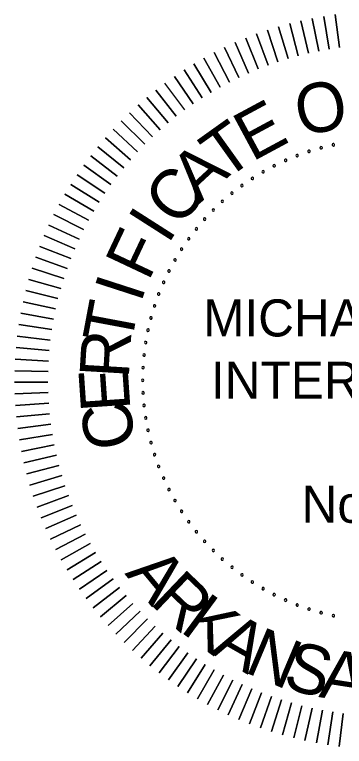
# Model space of a CAD drawing. Extents: x 185 to 5012, y 113 to 2127.
# Drawn here: x 2660.2 to 2771.5, y 179.4 to 426.3 of the extents above; entities that cross this region are included whole.
import ezdxf

# ---------------------------------------------------------------- set-up
doc = ezdxf.new("R2010")
doc.units = 0
doc.layers.add('STAMP_BOL', color=7, linetype='Continuous')

msp = doc.modelspace()

# ---------------------------------------------------------------- linework, layer by layer
at = {"layer": 'STAMP_BOL'}
for points in [[(2762.82, 414.03), (2760.66, 425.04)], [(2760.66, 425.04), (2762.82, 414.03)], [(2766.33, 414.66), (2764.51, 425.73)], [(2764.51, 425.73), (2766.33, 414.66)], [(2769.84, 415.18), (2768.38, 426.3)], [(2768.38, 426.3), (2769.84, 415.18)], [(2752.47, 411.48), (2749.28, 422.24)], [(2749.28, 422.24), (2752.47, 411.48)], [(2755.89, 412.44), (2753.04, 423.29)], [(2753.04, 423.29), (2755.89, 412.44)], [(2759.35, 413.28), (2756.84, 424.22)], [(2756.84, 424.22), (2759.35, 413.28)], [(2745.71, 409.24), (2741.85, 419.78)], [(2741.85, 419.78), (2745.71, 409.24)], [(2749.07, 410.41), (2745.55, 421.07)], [(2745.55, 421.07), (2749.07, 410.41)], [(2742.39, 407.97), (2738.21, 418.38)], [(2738.21, 418.38), (2742.39, 407.97)], [(2735.88, 405.11), (2731.05, 415.23)], [(2731.05, 415.23), (2735.88, 405.11)], [(2739.12, 406.59), (2734.6, 416.86)], [(2734.6, 416.86), (2739.12, 406.59)], [(2732.7, 403.52), (2727.55, 413.49)], [(2727.55, 413.49), (2732.7, 403.52)], [(2729.56, 401.84), (2724.1, 411.65)], [(2724.1, 411.65), (2729.56, 401.84)], [(2723.46, 398.19), (2717.4, 407.63)], [(2717.4, 407.63), (2723.46, 398.19)], [(2726.48, 400.06), (2720.72, 409.69)], [(2720.72, 409.69), (2726.48, 400.06)], [(2720.5, 396.22), (2714.14, 405.46)], [(2714.14, 405.46), (2720.5, 396.22)], [(2717.6, 394.16), (2710.95, 403.2)], [(2714.77, 392), (2707.84, 400.83)], [(2707.84, 400.83), (2714.77, 392)], [(2712.01, 389.77), (2704.8, 398.37)], [(2704.8, 398.37), (2712.01, 389.77)], [(2709.31, 387.44), (2701.85, 395.82)], [(2701.85, 395.82), (2709.31, 387.44)], [(2706.7, 385.03), (2698.97, 393.17)], [(2698.97, 393.17), (2706.7, 385.03)], [(2704.16, 382.54), (2696.18, 390.43)], [(2696.18, 390.43), (2704.16, 382.54)], [(2701.7, 379.97), (2693.47, 387.61)], [(2693.47, 387.61), (2701.7, 379.97)], [(2699.32, 377.33), (2690.86, 384.71)], [(2690.86, 384.71), (2699.32, 377.33)], [(2697.02, 374.61), (2688.34, 381.72)], [(2688.34, 381.72), (2697.02, 374.61)], [(2694.81, 371.83), (2685.91, 378.65)], [(2685.91, 378.65), (2694.81, 371.83)], [(2692.69, 368.97), (2683.58, 375.51)], [(2683.58, 375.51), (2692.69, 368.97)], [(2690.67, 366.05), (2681.35, 372.3)], [(2681.35, 372.3), (2690.67, 366.05)], [(2688.73, 363.06), (2679.22, 369.02)], [(2679.22, 369.02), (2688.73, 363.06)], [(2686.89, 360.02), (2677.2, 365.68)], [(2677.2, 365.68), (2686.89, 360.02)], [(2685.14, 356.92), (2675.28, 362.27)], [(2675.28, 362.27), (2685.14, 356.92)], [(2683.5, 353.77), (2673.47, 358.81)], [(2673.47, 358.81), (2683.5, 353.77)], [(2681.95, 350.57), (2671.77, 355.29)], [(2671.77, 355.29), (2681.95, 350.57)], [(2680.5, 347.32), (2670.18, 351.72)], [(2670.18, 351.72), (2680.5, 347.32)], [(2679.16, 344.02), (2668.7, 348.1)], [(2668.7, 348.1), (2679.16, 344.02)], [(2677.92, 340.69), (2667.34, 344.43)], [(2667.34, 344.43), (2677.92, 340.69)], [(2676.79, 337.32), (2666.1, 340.73)], [(2666.1, 340.73), (2676.79, 337.32)], [(2675.76, 333.91), (2664.97, 336.98)], [(2664.97, 336.98), (2675.76, 333.91)], [(2674.84, 330.48), (2663.96, 333.21)], [(2663.96, 333.21), (2674.84, 330.48)], [(2674.03, 327.01), (2663.07, 329.4)], [(2663.07, 329.4), (2674.03, 327.01)], [(2673.33, 323.53), (2662.29, 325.57)], [(2662.29, 325.57), (2673.33, 323.53)], [(2672.74, 320.02), (2661.64, 321.71)], [(2661.64, 321.71), (2672.74, 320.02)], [(2672.26, 316.5), (2661.11, 317.84)], [(2661.11, 317.84), (2672.26, 316.5)], [(2671.89, 312.96), (2660.71, 313.95)], [(2660.71, 313.95), (2671.89, 312.96)], [(2671.63, 309.41), (2660.42, 310.05)], [(2660.42, 310.05), (2671.63, 309.41)], [(2671.48, 305.86), (2660.26, 306.15)], [(2660.26, 306.15), (2671.48, 305.86)], [(2671.44, 302.3), (2660.22, 302.24)], [(2660.22, 302.24), (2671.44, 302.3)], [(2671.52, 298.75), (2660.3, 298.33)], [(2660.3, 298.33), (2671.52, 298.75)], [(2671.71, 295.19), (2660.51, 294.43)], [(2660.51, 294.43), (2671.71, 295.19)], [(2672, 291.65), (2660.84, 290.53)], [(2660.84, 290.53), (2672, 291.65)], [(2672.41, 288.12), (2661.29, 286.65)], [(2661.29, 286.65), (2672.41, 288.12)], [(2672.94, 284.6), (2661.86, 282.78)], [(2661.86, 282.78), (2672.94, 284.6)], [(2673.57, 281.1), (2662.55, 278.93)], [(2662.55, 278.93), (2673.57, 281.1)], [(2674.31, 277.62), (2663.37, 275.11)], [(2663.37, 275.11), (2674.31, 277.62)], [(2675.16, 274.17), (2664.3, 271.31)], [(2664.3, 271.31), (2675.16, 274.17)], [(2676.11, 270.74), (2665.35, 267.55)], [(2665.35, 267.55), (2676.11, 270.74)], [(2677.18, 267.35), (2666.52, 263.82)], [(2666.52, 263.82), (2677.18, 267.35)], [(2678.35, 263.99), (2667.81, 260.13)], [(2667.81, 260.13), (2678.35, 263.99)], [(2679.63, 260.67), (2669.21, 256.48)], [(2669.21, 256.48), (2679.63, 260.67)], [(2681, 257.39), (2670.73, 252.88)], [(2670.73, 252.88), (2681, 257.39)], [(2682.49, 254.16), (2672.36, 249.32)], [(2672.36, 249.32), (2682.49, 254.16)], [(2684.07, 250.97), (2674.1, 245.82)], [(2674.1, 245.82), (2684.07, 250.97)], [(2685.75, 247.84), (2675.95, 242.38)], [(2675.95, 242.38), (2685.75, 247.84)], [(2687.53, 244.76), (2677.9, 238.99)], [(2677.9, 238.99), (2687.53, 244.76)], [(2689.41, 241.73), (2679.96, 235.67)], [(2679.96, 235.67), (2689.41, 241.73)], [(2691.37, 238.77), (2682.13, 232.41)], [(2682.13, 232.41), (2691.37, 238.77)], [(2693.44, 235.87), (2684.39, 229.23)], [(2684.39, 229.23), (2693.44, 235.87)], [(2695.59, 233.04), (2686.76, 226.11)], [(2686.76, 226.11), (2695.59, 233.04)], [(2697.83, 230.28), (2689.22, 223.08)], [(2689.22, 223.08), (2697.83, 230.28)], [(2700.15, 227.59), (2691.77, 220.12)], [(2691.77, 220.12), (2700.15, 227.59)], [(2702.56, 224.97), (2694.42, 217.24)], [(2694.42, 217.24), (2702.56, 224.97)], [(2705.05, 222.43), (2697.16, 214.45)], [(2697.16, 214.45), (2705.05, 222.43)], [(2707.62, 219.97), (2699.98, 211.75)], [(2699.98, 211.75), (2707.62, 219.97)], [(2702.89, 209.13), (2710.26, 217.59)], [(2710.26, 217.59), (2702.89, 209.13)], [(2705.87, 206.61), (2712.98, 215.29)], [(2712.98, 215.29), (2705.87, 206.61)], [(2708.94, 204.18), (2715.77, 213.09)], [(2715.77, 213.09), (2708.94, 204.18)], [(2712.08, 201.85), (2718.62, 210.97)], [(2718.62, 210.97), (2712.08, 201.85)], [(2715.29, 199.62), (2721.54, 208.94)], [(2721.54, 208.94), (2715.29, 199.62)], [(2718.57, 197.49), (2724.53, 207)], [(2724.53, 207), (2718.57, 197.49)], [(2721.91, 195.47), (2727.57, 205.16)], [(2727.57, 205.16), (2721.91, 195.47)], [(2725.32, 193.55), (2730.67, 203.42)], [(2730.67, 203.42), (2725.32, 193.55)], [(2728.78, 191.74), (2733.82, 201.77)], [(2733.82, 201.77), (2728.78, 191.74)], [(2732.3, 190.04), (2737.02, 200.22)], [(2737.02, 200.22), (2732.3, 190.04)], [(2735.88, 188.45), (2740.27, 198.78)], [(2740.27, 198.78), (2735.88, 188.45)], [(2739.5, 186.98), (2743.57, 197.43)], [(2743.57, 197.43), (2739.5, 186.98)], [(2743.16, 185.61), (2746.9, 196.19)], [(2746.9, 196.19), (2743.16, 185.61)], [(2746.87, 184.37), (2750.27, 195.06)], [(2750.27, 195.06), (2746.87, 184.37)], [(2750.61, 183.24), (2753.68, 194.03)], [(2753.68, 194.03), (2750.61, 183.24)], [(2754.38, 182.23), (2757.11, 193.12)], [(2757.11, 193.12), (2754.38, 182.23)], [(2758.19, 181.34), (2760.58, 192.3)], [(2760.58, 192.3), (2758.19, 181.34)], [(2762.02, 180.57), (2764.06, 191.6)], [(2764.06, 191.6), (2762.02, 180.57)], [(2765.88, 179.92), (2767.57, 191.01)], [(2767.57, 191.01), (2765.88, 179.92)], [(2769.75, 179.39), (2771.1, 190.53)], [(2771.1, 190.53), (2769.75, 179.39)]]:
    msp.add_lwpolyline(points, dxfattribs=at)
for centre, start, end in [((2767.77, 382.37), 12, 192), ((2759.56, 380.17), 18, 198), ((2759.56, 380.17), 198, 18), ((2763.64, 381.38), 15, 195), ((2763.64, 381.38), 195, 15), ((2767.77, 382.37), 192, 12), ((2755.55, 378.75), 21, 201), ((2755.55, 378.75), 201, 21), ((2747.79, 375.3), 27, 207), ((2747.79, 375.3), 207, 27), ((2751.63, 377.13), 24, 204), ((2751.63, 377.13), 204, 24), ((2744.05, 373.27), 30, 210), ((2744.05, 373.27), 210, 30), ((2740.43, 371.04), 33, 213), ((2740.43, 371.04), 213, 33), ((2736.92, 368.64), 36, 216), ((2736.92, 368.64), 216, 36), ((2733.55, 366.05), 39, 219), ((2733.55, 366.05), 219, 39), ((2730.32, 363.29), 42, 222), ((2730.32, 363.29), 222, 42), ((2727.23, 360.36), 45, 225), ((2727.23, 360.36), 225, 45), ((2724.31, 357.28), 48, 228), ((2724.31, 357.28), 228, 48), ((2721.54, 354.04), 51, 231), ((2721.54, 354.04), 231, 51), ((2718.96, 350.67), 54, 234), ((2718.96, 350.67), 234, 54), ((2716.55, 347.16), 57, 237), ((2716.55, 347.16), 237, 57), ((2714.33, 343.54), 60, 240), ((2714.33, 343.54), 240, 60), ((2712.3, 339.8), 63, 243), ((2712.3, 339.8), 243, 63), ((2710.47, 335.97), 66, 246), ((2710.47, 335.97), 246, 66), ((2708.84, 332.04), 69, 249), ((2708.84, 332.04), 249, 69), ((2707.42, 328.03), 72, 252), ((2707.42, 328.03), 252, 72), ((2706.21, 323.95), 75, 255), ((2706.21, 323.95), 255, 75), ((2705.22, 319.82), 78, 258), ((2705.22, 319.82), 258, 78), ((2704.44, 315.64), 81, 261), ((2704.44, 315.64), 261, 81), ((2703.89, 311.42), 84, 264), ((2703.89, 311.42), 264, 84), ((2703.56, 307.18), 87, 267), ((2703.56, 307.18), 267, 87), ((2703.44, 302.93), 90, 270), ((2703.44, 302.93), 270, 90), ((2703.56, 298.68), 93, 273), ((2703.56, 298.68), 273, 93), ((2703.89, 294.44), 96, 276), ((2703.89, 294.44), 276, 96), ((2704.44, 290.23), 99, 279), ((2704.44, 290.23), 279, 99), ((2705.22, 286.05), 102, 282), ((2705.22, 286.05), 282, 102), ((2706.21, 281.91), 105, 285), ((2706.21, 281.91), 285, 105), ((2707.42, 277.84), 108, 288), ((2707.42, 277.84), 288, 108), ((2708.84, 273.83), 111, 291), ((2708.84, 273.83), 291, 111), ((2710.47, 269.9), 114, 294), ((2710.47, 269.9), 294, 114), ((2712.3, 266.06), 117, 297), ((2712.3, 266.06), 297, 117), ((2714.33, 262.32), 120, 300), ((2714.33, 262.32), 300, 120), ((2716.55, 258.7), 123, 303), ((2716.55, 258.7), 303, 123), ((2718.96, 255.2), 126, 306), ((2718.96, 255.2), 306, 126), ((2721.54, 251.82), 129, 309), ((2721.54, 251.82), 309, 129), ((2724.31, 248.59), 132, 312), ((2724.31, 248.59), 312, 132), ((2727.23, 245.5), 135, 315), ((2727.23, 245.5), 315, 135), ((2730.32, 242.58), 138, 318), ((2730.32, 242.58), 318, 138), ((2733.55, 239.82), 141, 321), ((2733.55, 239.82), 321, 141), ((2736.92, 237.23), 144, 324), ((2736.92, 237.23), 324, 144), ((2740.43, 234.82), 147, 327), ((2740.43, 234.82), 327, 147), ((2744.05, 232.6), 150, 330), ((2744.05, 232.6), 330, 150), ((2747.79, 230.57), 153, 333), ((2747.79, 230.57), 333, 153), ((2751.63, 228.74), 156, 336), ((2751.63, 228.74), 336, 156), ((2755.55, 227.11), 159, 339), ((2755.55, 227.11), 339, 159), ((2759.56, 225.69), 162, 342), ((2759.56, 225.69), 342, 162), ((2763.64, 224.48), 345, 165), ((2763.64, 224.48), 165, 345), ((2767.77, 223.49), 168, 348), ((2767.77, 223.49), 348, 168)]:
    msp.add_arc(centre, 0.417, start, end, dxfattribs=at)

# ---------------------------------------------------------------- texts
for s, rotation, p in [('O', 10.7295, (2756.5, 385.26)), ('E', 28.279, (2740.32, 376.53)), ('T', 35.5725, (2731.01, 370.07)), ('A', 42.8659, (2722.55, 362.37)), ('C', 50.1594, (2715.54, 354.04)), ('I', 57.4529, (2711.91, 348.47)), ('F', 64.7464, (2705.37, 336.01)), ('I', 72.0398, (2702.79, 328.68)), ('T', 79.3333, (2699.48, 314.32)), ('R', 86.6268, (2698.71, 303.3)), ('E', 93.9203, (2699.33, 292.89)), ('C', 101.2137, (2701.46, 281.3)), ('A', 309.5859, (2697.19, 237.67)), ('R', 316.3356, (2705.47, 227.84)), ('K', 323.6428, (2715.67, 218.38)), ('A', 330.3925, (2726.08, 210.85)), ('N', 337.1422, (2737.31, 204.61)), ('S', 344.4494, (2750.2, 199.38)), ('A', 351.1991, (2762.61, 196.05))]:
    msp.add_text(s, height=16.67, rotation=rotation, dxfattribs=at).set_placement(p)
for s, height, p in [('MICHAEL BAKER', 12.5016, (2723.83, 317.71)), (' INTERNATIONAL', 12.5016, (2721.82, 296.69)), (' No. 1126', 12.502, (2752.39, 254.83))]:
    msp.add_text(s, height=height, dxfattribs=at).set_placement(p)

doc.saveas('drawing.dxf')
